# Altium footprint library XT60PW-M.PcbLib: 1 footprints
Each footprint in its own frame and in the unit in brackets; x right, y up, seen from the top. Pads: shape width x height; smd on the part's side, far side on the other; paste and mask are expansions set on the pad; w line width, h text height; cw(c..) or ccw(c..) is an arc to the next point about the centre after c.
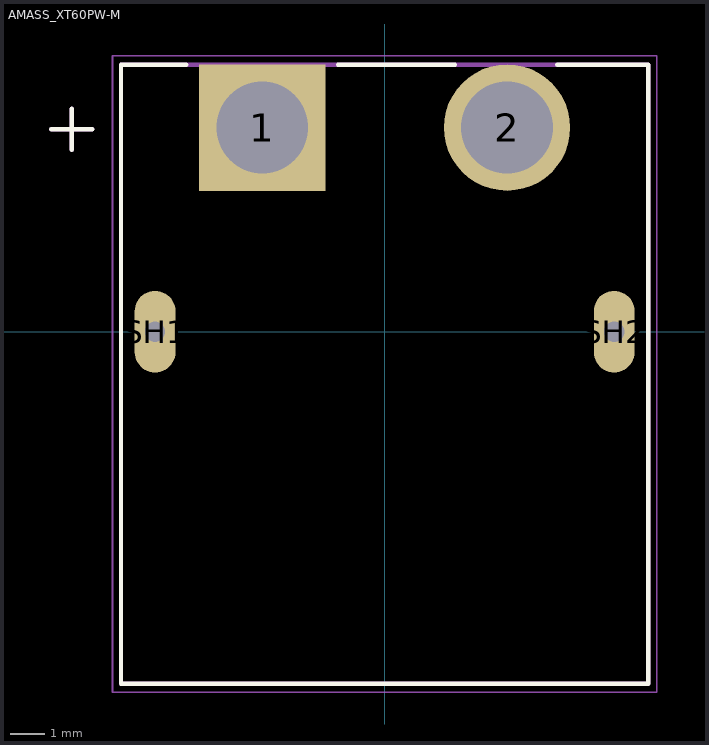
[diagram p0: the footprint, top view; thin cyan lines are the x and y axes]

## AMASS_XT60PW-M [mm]
height 8.4
pads (4):
  rect 3.716x3.716 / inner round 3.716 / far side rect 3.716x3.716 hole 2.7 mask+0.102: 1(-3.6,6)
  round 3.716 hole 2.7 mask+0.102: 2(3.6,6)
  oval 1.2x2.4 hole 0.6 square mask+0.102: SH1(-6.75,0) SH2(6.75,0)
Top Overlay:
  lines w0.127: -9.8,5.95 -8.6,5.95 ; -9.2,5.35 -9.2,6.55 ; -5.828,7.85 -7.75,7.85 -7.75,-10.35 7.75,-10.35 7.75,7.85 5.078,7.85 ; -1.372,7.85 2.072,7.85
Assembly Top:
  lines w0.127: -9.8,5.95 -8.6,5.95 ; -9.2,5.35 -9.2,6.55 ; -7.75,-10.35 -7.75,7.85 7.75,7.85 7.75,-10.35 -7.75,-10.35
Courtyard Top:
  lines w0.05: -8,-10.6 -8,8.11 8,8.11 8,-10.6 -8,-10.6
3D body "step_temp.STEP": height 8.4, standoff -2.55, extent -7.75,-10.35 7.75,7.85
